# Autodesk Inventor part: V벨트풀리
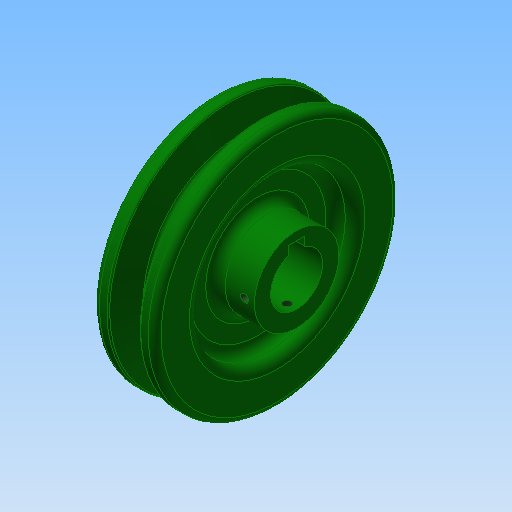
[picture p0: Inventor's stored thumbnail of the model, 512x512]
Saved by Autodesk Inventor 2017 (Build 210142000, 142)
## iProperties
Created: 2015-11
Part Number: V벨트풀리
Material: 강철, 탄소
Document SubType Name: Modeling
Designer: mduedu
Density: 1 g/cm^3
Appearance: 진녹색
Author: mduedu
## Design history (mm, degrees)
sketch "스케치1"
  geometry: L1 (-9.5, 0)-(9.5, 0); L2 (0, 0)-(0, 37.7); L3 (-4.825, 37.7)-(-9.5, 37.7); L4 (-9.5, 37.7)-(-9.5, 0); L5 (0, 28.7)-(-2.074, 28.7); L6 (-2.074, 28.7)-(-4.825, 37.7); L7 (4.825, 37.7)-(9.5, 37.7); L8 (9.5, 37.7)-(9.5, 0); L9 (0, 28.7)-(2.074, 28.7); L10 (2.074, 28.7)-(4.825, 37.7); L11 (-9.5, 35)-(9.5, 35); 3 further points
  constraints: 22 end point, 7 point on line, 4 perpendicular, 3 symmetric about line, 1 coincident, 1 horizontal, 1 horizontal alignment, 1 midpoint, 1 vertical
  dimensions: "d0" = 19 distance of L1.start L1.end; "d2" = 75.4 diameter of L2.end L1 (derived); "d3" = 34 deg angle of L10 L6; "d4" = 6.3 distance between parallel lines of L11 L9; "d5" = 2.7 distance between parallel lines of L7 L11; "d6" = 8 distance of point (4, 35) point (-4, 35); "d7" = 70 diameter of L11 L1
revolve "회전1" sketch "스케치1" stored, may be unused: angle "d8" = 90 deg
sketch "스케치2"
  geometry: C1 r 24 at (0, 0); C2 r 13 at (0, 0); 1 further point
  constraints: 2 centre point, 2 coincident
  dimensions: "d9" = 48 diameter of C1; "d10" = 26 diameter of C2
extrude "돌출1" cut sketch "스케치2" distance "d11" = 6; taper "d12" = 0 deg
extrude "돌출3" join sketch "스케치2" distance "d37" = 6; taper "d38" = 0 deg
fillet "모깎기1" dims "d13" = 3
fillet "모깎기2" dims "d14" = 3
fillet "모깎기3" dims "d15" = 1, "d16" = 0.5, "d17" = 2
hole "구멍1" diameter "d20" = 16; stored, may be unused: countersink angle "d24" = 90 deg, drill point angle "d26" = 118 deg; dims "d21" = 6, "d22" = 4, "d23" = 2, "d25" = 8, "d53" = 10, "d54" = 10
sketch "스케치3"
  geometry: L1 (-2.5, 0)-(2.5, 0); L2 (2.5, 0)-(2.5, 10.3); L3 (2.5, 10.3)-(-2.5, 10.3); L4 (-2.5, 10.3)-(-2.5, 0); 2 further points
  constraints: 8 end point, 2 parallel, 1 coincident, 1 horizontal, 1 midpoint, 1 perpendicular
  dimensions: "d27" = 5 distance of L2.end L3.end; "d29" = 10.3 distance of L3.end L1.start
extrude "돌출2" cut sketch "스케치3" stored distance "d30" = 6; taper "d31" = 0 deg
node "작업 평면1"
sketch "스케치4"
  geometry: L1 (19, -27)-(19, 27) reference; 2 further points
  constraints: 1 horizontal alignment
  dimensions: "d52" = 22 distance from line of L1 point (-3, 0)
hole "구멍2" sketch "스케치4" at (-3, 0) diameter "d42" = 2.459; stored, may be unused: countersink angle "d46" = 90 deg, drill point angle "d48" = 118 deg; dims "d43" = 6, "d44" = 4, "d45" = 2, "d47" = 8
node "솔리드1"
mirror "대칭1"
pattern_circular "원형 패턴1" dims angle "d62" = 90 deg
